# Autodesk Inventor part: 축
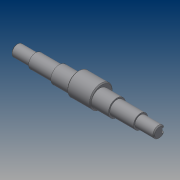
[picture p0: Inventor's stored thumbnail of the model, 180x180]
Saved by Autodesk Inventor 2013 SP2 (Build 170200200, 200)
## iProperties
Created: 2014-12
Part Number: 축
Material: Generic
Document SubType Name: Modeling
Designer: CADB301
Density: 1 g/cm^3
Author: CADB301
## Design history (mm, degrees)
sketch "스케치1"
  geometry: L1 (-75.5, 0)-(75.5, 0); L2 (-75.5, 0)-(-75.5, 6); L3 (-75.5, 6)-(-55.5, 6); L4 (-55.5, 6)-(-55.5, 7.5); L5 (-55.5, 7.5)-(-30.5, 7.5); L6 (-30.5, 7.5)-(-30.5, 9); L7 (-30.5, 9)-(30.5, 9); L8 (30.5, 9)-(30.5, 7.5); L9 (30.5, 7.5)-(55.5, 7.5); L10 (55.5, 7.5)-(55.5, 6); L11 (55.5, 6)-(75.5, 6); L12 (75.5, 6)-(75.5, 0); L13 (-12.5, 14)-(12.5, 14); L14 (12.5, 14)-(12.5, 2); L15 (12.5, 2)-(-12.5, 2); L16 (-12.5, 2)-(-12.5, 14); L17 (-75.5, 6)-(-61.5, 6); L18 (-61.5, 6)-(-61.5, 3); L19 (-61.5, 3)-(-75.5, 3); L20 (-75.5, 3)-(-75.5, 6); L21 (75.5, 6)-(61.5, 6); L22 (61.5, 6)-(61.5, 3); L23 (61.5, 3)-(75.5, 3); L24 (75.5, 3)-(75.5, 6); 2 further points
  constraints: 48 end point, 13 parallel, 6 perpendicular, 4 horizontal, 3 collinear, 1 coincident, 1 midpoint
  dimensions: "d0" = 151 distance of L1.start L1.end; "d1" = 12 diameter of L3 L1; "d3" = 15 diameter of L5 L1; "d4" = 18 diameter of L7 L1; "d5" = 20 distance of L2.end L3.end; "d6" = 25 distance of L4.end L5.end; "d8" = 20 distance of L10.end L11.end; "d9" = 25 distance of L8.end L9.end; "d10" = 4 diameter of L15 L1; "d11" = 24 diameter of L13 L15; "d12" = 18 distance between parallel lines of L6 L16; "d13" = 18 distance between parallel lines of L8 L14; "d14" = 3 distance of L17.end L18.end; "d15" = 14 distance of L18.end L19.end; "d16" = 14 distance of L22.end L23.end; "d17" = 3 distance of L21.end L22.end
revolve "회전1" stored, may be unused: angle "d18" = 90 deg
revolve "회전2" stored, may be unused: angle "d19" = 90 deg
extrude "돌출1" cut sketch "스케치1" stored distance "d20" = 5; taper "d21" = 0 deg
fillet "모깎기1" dims "d22" = 2.5
chamfer "모따기1" distance "d23" = 1; stored, may be unused: second distance "d24" = 2, angle "d25" = 45 deg
node "솔리드1"
